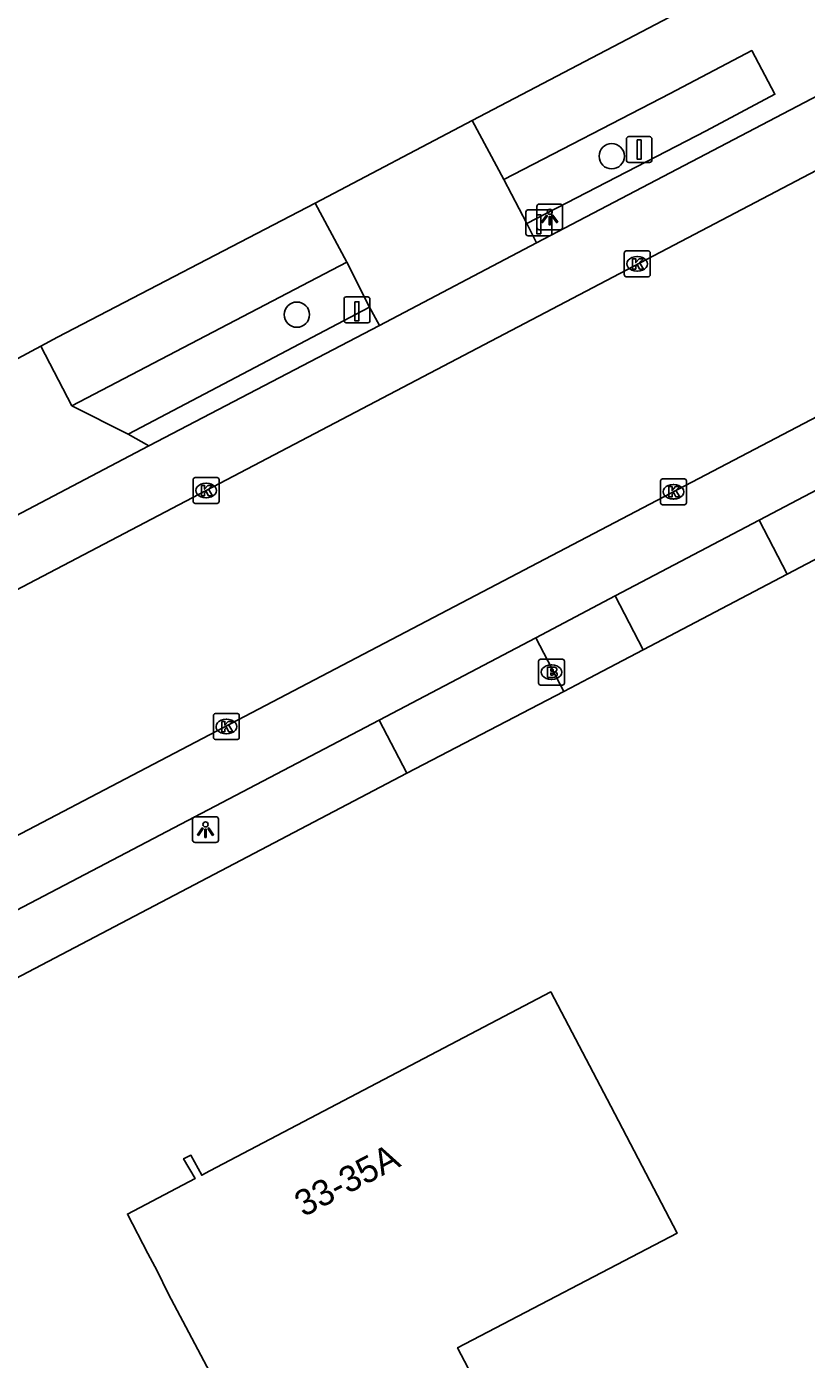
# Model space of a CAD drawing. Extents: x 157692 to 159670, y 381454 to 383289.
# Drawn here: x 158347.4 to 158377.6, y 381827.3 to 381878.9 of the extents above; entities that cross this region are included whole.
import ezdxf

# ---------------------------------------------------------------- set-up
doc = ezdxf.new("R2010")
doc.units = 0
for name, color, linetype in [('IMGEO_Boom', 7, 'Continuous'), ('IMGEO_Brandkraan', 7, 'Continuous'), ('IMGEO_Kolk', 7, 'Continuous'), ('IMGEO_Lichtpunt', 7, 'Continuous'), ('IMGEO_Paal', 7, 'Continuous'), ('IMGEO_Pand', 7, 'Continuous'), ('IMGEO_Pand_nummerreeks', 7, 'Continuous'), ('IMGEO_Rijbaan_lokaal_gesloten', 7, 'Continuous'), ('IMGEO_Rijbaan_lokaal_open', 7, 'Continuous'), ('IMGEO_Verkeersbordpaal', 7, 'Continuous'), ('IMGEO_Voetpad_open', 7, 'Continuous')]:
    doc.layers.add(name, color=color, linetype=linetype)

msp = doc.modelspace()

# ---------------------------------------------------------------- linework, layer by layer
at = {"layer": 'IMGEO_Boom'}
for centre in [(158370.043, 381873.88), (158357.856, 381867.748)]:
    msp.add_circle(centre, 0.489, dxfattribs=at)
at = {"layer": 'IMGEO_Brandkraan'}
for p, q in [((158367.213, 381853.487), (158367.213, 381854.339)), ((158367.288, 381854.413), (158368.14, 381854.413)), ((158368.214, 381854.339), (158368.214, 381853.487)), ((158367.701, 381854.193), (158367.726, 381854.193)), ((158368.14, 381853.413), (158367.288, 381853.413)), ((158367.724, 381853.633), (158367.699, 381853.633))]:
    msp.add_line(p, q, dxfattribs=at)
for points in [[(158367.213, 381853.487), (158367.213, 381854.339)], [(158367.288, 381854.413), (158368.14, 381854.413)], [(158368.214, 381854.339), (158368.214, 381853.487)], [(158367.561, 381854.113), (158367.561, 381853.713), (158367.774, 381853.713)], [(158367.792, 381854.113), (158367.561, 381854.113)], [(158367.74, 381854.032), (158367.686, 381854.032), (158367.686, 381853.956)], [(158367.686, 381853.956), (158367.739, 381853.956)], [(158367.748, 381853.88), (158367.686, 381853.88), (158367.686, 381853.799)], [(158367.686, 381853.799), (158367.748, 381853.799)], [(158368.14, 381853.413), (158367.288, 381853.413)]]:
    msp.add_lwpolyline(points, dxfattribs=at)
for centre, radius, start, end in [((158367.29, 381854.337), 0.0765, 91.552, 178.448), ((158367.29, 381854.337), 0.0765, 91.552, 178.448), ((158368.138, 381854.337), 0.0765, 1.552, 88.448), ((158368.138, 381854.337), 0.0765, 1.552, 88.448), ((158367.741, 381853.994), 0.0379, 267.8285, 90.9355), ((158367.749, 381853.839), 0.0404, 269.8759, 90.5077), ((158367.78, 381853.964), 0.251, 268.6676, 293.5347), ((158367.796, 381853.968), 0.145, 59.4692, 91.5367), ((158367.821, 381854.015), 0.0922, 285.5137, 58.1501), ((158367.826, 381853.823), 0.105, 301.3115, 78.989), ((158367.29, 381853.489), 0.0765, 181.552, 268.448), ((158367.29, 381853.489), 0.0765, 181.552, 268.448), ((158368.138, 381853.489), 0.0765, 271.552, 358.448), ((158368.138, 381853.489), 0.0765, 271.552, 358.448)]:
    msp.add_arc(centre, radius, start, end, dxfattribs=at)
for centre, major_axis, ratio, start_param, end_param in [((158367.7, 381853.913), (-0.387, 0.002), 0.722429, 4.712389, 7.853982), ((158367.725, 381853.913), (-0.39, 0.002), 0.717154, 1.570796, 4.712389)]:
    msp.add_ellipse(centre, major_axis=major_axis, ratio=ratio, start_param=start_param, end_param=end_param, dxfattribs=at)
at = {"layer": 'IMGEO_Kolk'}
for p, q in [((158370.606, 381870.214), (158371.458, 381870.214)), ((158370.531, 381869.288), (158370.531, 381870.14)), ((158371.019, 381869.994), (158371.044, 381869.994)), ((158371.532, 381870.14), (158371.532, 381869.288)), ((158371.458, 381869.214), (158370.606, 381869.214)), ((158371.042, 381869.434), (158371.017, 381869.434)), ((158353.916, 381861.443), (158354.768, 381861.443)), ((158353.841, 381860.517), (158353.841, 381861.369)), ((158354.329, 381861.223), (158354.354, 381861.223)), ((158354.842, 381861.369), (158354.842, 381860.517)), ((158371.935, 381860.468), (158371.935, 381861.32)), ((158372.01, 381861.394), (158372.862, 381861.394)), ((158372.423, 381861.174), (158372.448, 381861.174)), ((158372.936, 381861.32), (158372.936, 381860.468)), ((158354.768, 381860.443), (158353.916, 381860.443)), ((158354.352, 381860.663), (158354.327, 381860.663)), ((158372.862, 381860.394), (158372.01, 381860.394)), ((158372.446, 381860.614), (158372.421, 381860.614)), ((158354.626, 381851.384), (158354.626, 381852.236)), ((158354.701, 381852.31), (158355.553, 381852.31)), ((158355.627, 381852.236), (158355.627, 381851.384)), ((158355.114, 381852.09), (158355.139, 381852.09)), ((158355.553, 381851.31), (158354.701, 381851.31)), ((158355.137, 381851.53), (158355.112, 381851.53))]:
    msp.add_line(p, q, dxfattribs=at)
for points in [[(158370.606, 381870.214), (158371.458, 381870.214)], [(158370.531, 381869.288), (158370.531, 381870.14)], [(158370.852, 381869.914), (158370.975, 381869.914), (158370.975, 381869.763), (158371.105, 381869.914), (158371.269, 381869.914), (158371.123, 381869.763), (158371.276, 381869.514), (158371.124, 381869.514), (158371.039, 381869.678), (158370.975, 381869.611), (158370.975, 381869.514), (158370.852, 381869.514), (158370.852, 381869.914)], [(158371.532, 381870.14), (158371.532, 381869.288)], [(158371.458, 381869.214), (158370.606, 381869.214)], [(158353.916, 381861.443), (158354.768, 381861.443)], [(158353.841, 381860.517), (158353.841, 381861.369)], [(158354.162, 381861.143), (158354.285, 381861.143), (158354.285, 381860.992), (158354.415, 381861.143), (158354.579, 381861.143), (158354.433, 381860.992), (158354.586, 381860.743), (158354.434, 381860.743), (158354.349, 381860.907), (158354.285, 381860.84), (158354.285, 381860.743), (158354.162, 381860.743), (158354.162, 381861.143)], [(158354.842, 381861.369), (158354.842, 381860.517)], [(158371.935, 381860.468), (158371.935, 381861.32)], [(158372.01, 381861.394), (158372.862, 381861.394)], [(158372.256, 381861.094), (158372.379, 381861.094), (158372.379, 381860.943), (158372.509, 381861.094), (158372.673, 381861.094), (158372.527, 381860.943), (158372.68, 381860.694), (158372.528, 381860.694), (158372.443, 381860.858), (158372.379, 381860.791), (158372.379, 381860.694), (158372.256, 381860.694), (158372.256, 381861.094)], [(158372.936, 381861.32), (158372.936, 381860.468)], [(158354.768, 381860.443), (158353.916, 381860.443)], [(158372.862, 381860.394), (158372.01, 381860.394)], [(158354.626, 381851.384), (158354.626, 381852.236)], [(158354.701, 381852.31), (158355.553, 381852.31)], [(158355.627, 381852.236), (158355.627, 381851.384)], [(158354.947, 381852.01), (158355.07, 381852.01), (158355.07, 381851.859), (158355.2, 381852.01), (158355.364, 381852.01), (158355.218, 381851.859), (158355.371, 381851.61), (158355.219, 381851.61), (158355.134, 381851.774), (158355.07, 381851.707), (158355.07, 381851.61), (158354.947, 381851.61), (158354.947, 381852.01)], [(158355.553, 381851.31), (158354.701, 381851.31)]]:
    msp.add_lwpolyline(points, dxfattribs=at)
for centre, start, end in [((158370.608, 381870.138), 91.552, 178.448), ((158370.608, 381870.138), 91.552, 178.448), ((158371.456, 381870.138), 1.552, 88.448), ((158371.456, 381870.138), 1.552, 88.448), ((158370.608, 381869.29), 181.552, 268.448), ((158370.608, 381869.29), 181.552, 268.448), ((158371.456, 381869.29), 271.552, 358.448), ((158371.456, 381869.29), 271.552, 358.448), ((158353.918, 381861.367), 91.552, 178.448), ((158353.918, 381861.367), 91.552, 178.448), ((158354.766, 381861.367), 1.552, 88.448), ((158354.766, 381861.367), 1.552, 88.448), ((158372.012, 381861.318), 91.552, 178.448), ((158372.012, 381861.318), 91.552, 178.448), ((158372.86, 381861.318), 1.552, 88.448), ((158372.86, 381861.318), 1.552, 88.448), ((158353.918, 381860.519), 181.552, 268.448), ((158353.918, 381860.519), 181.552, 268.448), ((158354.766, 381860.519), 271.552, 358.448), ((158354.766, 381860.519), 271.552, 358.448), ((158372.012, 381860.47), 181.552, 268.448), ((158372.012, 381860.47), 181.552, 268.448), ((158372.86, 381860.47), 271.552, 358.448), ((158372.86, 381860.47), 271.552, 358.448), ((158354.703, 381852.234), 91.552, 178.448), ((158354.703, 381852.234), 91.552, 178.448), ((158355.551, 381852.234), 1.552, 88.448), ((158355.551, 381852.234), 1.552, 88.448), ((158354.703, 381851.386), 181.552, 268.448), ((158354.703, 381851.386), 181.552, 268.448), ((158355.551, 381851.386), 271.552, 358.448), ((158355.551, 381851.386), 271.552, 358.448)]:
    msp.add_arc(centre, 0.0765, start, end, dxfattribs=at)
for centre, major_axis, ratio, start_param, end_param in [((158371.018, 381869.714), (-0.387, 0.002), 0.722429, 4.712389, 7.853982), ((158371.043, 381869.714), (-0.39, 0.002), 0.717154, 1.570796, 4.712389), ((158354.328, 381860.943), (-0.387, 0.002), 0.722429, 4.712389, 7.853982), ((158354.353, 381860.943), (-0.39, 0.002), 0.717154, 1.570796, 4.712389), ((158372.422, 381860.894), (-0.387, 0.002), 0.722429, 4.712389, 7.853982), ((158372.447, 381860.894), (-0.39, 0.002), 0.717154, 1.570796, 4.712389), ((158355.113, 381851.81), (-0.387, 0.002), 0.722429, 4.712389, 7.853982), ((158355.138, 381851.81), (-0.39, 0.002), 0.717154, 1.570796, 4.712389)]:
    msp.add_ellipse(centre, major_axis=major_axis, ratio=ratio, start_param=start_param, end_param=end_param, dxfattribs=at)
at = {"layer": 'IMGEO_Lichtpunt'}
for p, q in [((158367.144, 381871.934), (158367.144, 381871.127)), ((158367.144, 381871.934), (158367.144, 381871.127)), ((158368.046, 381872.029), (158367.238, 381872.029)), ((158368.046, 381872.029), (158367.238, 381872.029)), ((158368.14, 381871.127), (158368.14, 381871.934)), ((158368.14, 381871.127), (158368.14, 381871.934)), ((158367.238, 381871.033), (158368.046, 381871.033)), ((158367.238, 381871.033), (158368.046, 381871.033)), ((158353.822, 381848.223), (158353.822, 381847.416)), ((158353.822, 381848.223), (158353.822, 381847.416)), ((158354.724, 381848.318), (158353.916, 381848.318)), ((158354.724, 381848.318), (158353.916, 381848.318)), ((158354.818, 381847.416), (158354.818, 381848.223)), ((158354.818, 381847.416), (158354.818, 381848.223)), ((158353.916, 381847.322), (158354.724, 381847.322)), ((158353.916, 381847.322), (158354.724, 381847.322))]:
    msp.add_line(p, q, dxfattribs=at)
for points in [[(158367.518, 381871.598), (158367.557, 381871.57), (158367.369, 381871.308), (158367.331, 381871.335), (158367.518, 381871.598)], [(158367.62, 381871.55), (158367.667, 381871.55), (158367.667, 381871.228), (158367.62, 381871.228), (158367.62, 381871.55)], [(158367.73, 381871.57), (158367.768, 381871.597), (158367.955, 381871.335), (158367.916, 381871.307), (158367.73, 381871.57)], [(158354.196, 381847.887), (158354.235, 381847.859), (158354.047, 381847.597), (158354.009, 381847.624), (158354.196, 381847.887)], [(158354.298, 381847.839), (158354.345, 381847.839), (158354.345, 381847.517), (158354.298, 381847.517), (158354.298, 381847.839)], [(158354.408, 381847.859), (158354.446, 381847.886), (158354.633, 381847.624), (158354.594, 381847.596), (158354.408, 381847.859)]]:
    msp.add_lwpolyline(points, dxfattribs=at)
for centre in [(158367.643, 381871.732), (158354.321, 381848.021)]:
    msp.add_circle(centre, 0.0994, dxfattribs=at)
for centre, start, end in [((158367.238, 381871.934), 90, 180), ((158367.238, 381871.934), 90, 180), ((158368.046, 381871.934), 0, 90), ((158368.046, 381871.934), 0, 90), ((158367.238, 381871.127), 180, 270), ((158367.238, 381871.127), 180, 270), ((158368.046, 381871.127), 270, 0), ((158368.046, 381871.127), 270, 360), ((158353.916, 381848.223), 90, 180), ((158353.916, 381848.223), 90, 180), ((158354.724, 381848.223), 0, 90), ((158354.724, 381848.223), 0, 90), ((158353.916, 381847.416), 180, 270), ((158353.916, 381847.416), 180, 270), ((158354.724, 381847.416), 270, 0), ((158354.724, 381847.416), 270, 360)]:
    msp.add_arc(centre, 0.0946, start, end, dxfattribs=at)
at = {"layer": 'IMGEO_Paal'}
for p, q in [((158367.639, 381871.802), (158366.798, 381871.802)), ((158367.639, 381871.802), (158366.798, 381871.802)), ((158366.723, 381871.718), (158366.723, 381870.877)), ((158366.723, 381871.718), (158366.723, 381870.877)), ((158367.723, 381870.886), (158367.723, 381871.727)), ((158367.723, 381870.886), (158367.723, 381871.727)), ((158366.807, 381870.802), (158367.648, 381870.802)), ((158366.807, 381870.802), (158367.648, 381870.802)), ((158359.683, 381868.351), (158359.683, 381867.51)), ((158359.683, 381868.351), (158359.683, 381867.51)), ((158360.599, 381868.435), (158359.758, 381868.435)), ((158360.599, 381868.435), (158359.758, 381868.435)), ((158360.683, 381867.519), (158360.683, 381868.36)), ((158360.683, 381867.519), (158360.683, 381868.36)), ((158359.767, 381867.435), (158360.608, 381867.435)), ((158359.767, 381867.435), (158360.608, 381867.435))]:
    msp.add_line(p, q, dxfattribs=at)
for points in [[(158367.138, 381871.615), (158367.298, 381871.615), (158367.298, 381870.882), (158367.138, 381870.882), (158367.138, 381871.615)], [(158360.098, 381868.248), (158360.258, 381868.248), (158360.258, 381867.515), (158360.098, 381867.515), (158360.098, 381868.248)]]:
    msp.add_lwpolyline(points, dxfattribs=at)
for centre, start, end in [((158366.801, 381871.724), 92.4484, 184.2845), ((158366.801, 381871.724), 92.4484, 184.2845), ((158367.645, 381871.724), 2.4484, 94.2845), ((158367.645, 381871.724), 2.4484, 94.2845), ((158366.801, 381870.88), 182.4484, 274.2845), ((158366.801, 381870.88), 182.4484, 274.2845), ((158367.645, 381870.88), 272.4484, 4.2845), ((158367.645, 381870.88), 272.4484, 4.2845), ((158359.761, 381868.357), 92.4484, 184.2845), ((158359.761, 381868.357), 92.4484, 184.2845), ((158360.605, 381868.357), 2.4484, 94.2845), ((158360.605, 381868.357), 2.4484, 94.2845), ((158359.761, 381867.513), 182.4484, 274.2845), ((158359.761, 381867.513), 182.4484, 274.2845), ((158360.605, 381867.513), 272.4484, 4.2845), ((158360.605, 381867.513), 272.4484, 4.2845)]:
    msp.add_arc(centre, 0.0779, start, end, dxfattribs=at)
at = {"layer": 'IMGEO_Pand'}
msp.add_lwpolyline([(158367.446, 381770.704), (158368.459, 381768.773), (158389.286, 381779.728), (158364.077, 381827.77), (158372.578, 381832.209), (158370.005, 381837.115), (158367.683, 381841.542), (158354.483, 381834.611), (158354.173, 381834.448), (158353.754, 381835.222), (158353.473, 381835.085), (158353.915, 381834.314), (158351.297, 381832.94), (158352.093, 381831.422), (158352.45, 381830.742), (158352.88, 381829.87), (158355.968, 381824.024), (158343.042, 381817.238), (158345.364, 381812.81), (158361.826, 381781.42)], dxfattribs=at)
at = {"layer": 'IMGEO_Rijbaan_lokaal_gesloten'}
for points in [[(158275.635, 381819.726), (158303.732, 381834.411), (158354.339, 381860.942), (158456.473, 381914.515), (158458.149, 381915.386), (158462.356, 381917.596)], [(158287.161, 381816.195), (158340.401, 381844.12), (158462.964, 381908.32), (158465.398, 381909.602)]]:
    msp.add_lwpolyline(points, dxfattribs=at)
at = {"layer": 'IMGEO_Rijbaan_lokaal_open'}
for points in [[(158358.563, 381872.057), (158364.635, 381875.26)], [(158364.635, 381875.26), (158365.865, 381872.972)], [(158365.865, 381872.972), (158366.751, 381871.28)], [(158358.563, 381872.057), (158359.785, 381869.784)], [(158366.751, 381871.28), (158367.135, 381870.529)], [(158367.135, 381870.529), (158361.052, 381867.333)], [(158359.785, 381869.784), (158360.665, 381868.04)], [(158360.665, 381868.04), (158361.052, 381867.333)], [(158342.759, 381863.76), (158347.941, 381866.531)], [(158349.146, 381864.225), (158347.941, 381866.531)], [(158351.326, 381863.129), (158349.146, 381864.225)], [(158352.126, 381862.671), (158351.326, 381863.129)], [(158352.126, 381862.671), (158343.994, 381858.396)]]:
    msp.add_lwpolyline(points, dxfattribs=at)
at = {"layer": 'IMGEO_Verkeersbordpaal'}
for p, q in [((158370.61, 381873.738), (158370.61, 381874.538)), ((158370.61, 381874.538), (158370.61, 381873.738)), ((158370.71, 381874.638), (158371.5, 381874.638)), ((158371.5, 381874.638), (158370.71, 381874.638)), ((158371.6, 381874.538), (158371.6, 381873.738)), ((158371.6, 381873.738), (158371.6, 381874.538)), ((158371.5, 381873.638), (158370.71, 381873.638)), ((158370.71, 381873.638), (158371.5, 381873.638))]:
    msp.add_line(p, q, dxfattribs=at)
msp.add_lwpolyline([(158371.03, 381874.513), (158371.18, 381874.513), (158371.18, 381873.763), (158371.03, 381873.763), (158371.03, 381874.513)], dxfattribs=at)
for centre, start, end in [((158370.71, 381874.538), 90, 180), ((158370.71, 381874.538), 90, 180), ((158371.5, 381874.538), 0, 90), ((158371.5, 381874.538), 360, 90), ((158370.71, 381873.738), 180, 270), ((158370.71, 381873.738), 180, 270), ((158371.5, 381873.738), 270, 0), ((158371.5, 381873.738), 270, 0)]:
    msp.add_arc(centre, 0.1, start, end, dxfattribs=at)
at = {"layer": 'IMGEO_Voetpad_open'}
for points in [[(158364.635, 381875.26), (158392.478, 381889.849)], [(158367.135, 381870.529), (158394.949, 381885.105)], [(158366.751, 381871.28), (158373.694, 381874.863), (158376.362, 381876.274), (158375.465, 381877.969), (158372.304, 381876.312), (158365.865, 381872.972)], [(158375.752, 381859.796), (158401.117, 381873.133)], [(158347.941, 381866.531), (158348.596, 381866.872), (158358.563, 381872.057)], [(158402.221, 381871.049), (158376.84, 381857.708)], [(158349.146, 381864.225), (158359.785, 381869.784)], [(158360.665, 381868.04), (158351.326, 381863.129)], [(158361.052, 381867.333), (158352.126, 381862.671)], [(158375.752, 381859.796), (158370.176, 381856.864)], [(158376.84, 381857.708), (158375.752, 381859.796)], [(158376.84, 381857.708), (158371.263, 381854.776)], [(158367.101, 381855.247), (158370.176, 381856.864)], [(158370.176, 381856.864), (158371.263, 381854.776)], [(158367.101, 381855.247), (158361.043, 381852.051)], [(158368.188, 381853.16), (158367.101, 381855.247)], [(158371.263, 381854.776), (158369.169, 381853.676), (158368.188, 381853.16)], [(158368.188, 381853.16), (158362.112, 381850.005)], [(158325.276, 381833.312), (158361.043, 381852.051)], [(158361.043, 381852.051), (158362.112, 381850.005)], [(158362.112, 381850.005), (158326.367, 381831.251)]]:
    msp.add_lwpolyline(points, dxfattribs=at)

# ---------------------------------------------------------------- texts
at = {"layer": 'IMGEO_Pand_nummerreeks'}
msp.add_text('33-35A', height=1, rotation=27.6968, dxfattribs=at).set_placement((158358.112, 381832.813))

doc.saveas('drawing.dxf')
